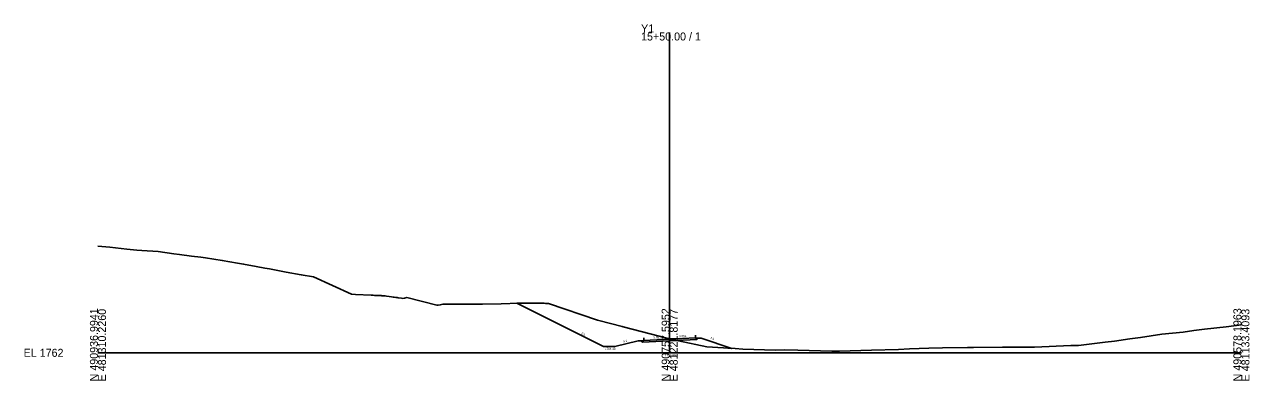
# Model space of a CAD drawing. Extents: x -26 to 403, y -10 to 6561.
# Drawn here: x -25.7 to 402.8, y 5490.3 to 5614.9 of the extents above; entities that cross this region are included whole.
import ezdxf

# ---------------------------------------------------------------- set-up
doc = ezdxf.new("R2010")
doc.units = 0
for name, color, linetype in [('Exist Cross Section Cell', 7, 'Continuous'), ('Exist XS Center Line Elevation Label', 7, 'Continuous'), ('Exist XS Ground Line', 7, 'Continuous'), ('Prop Road Sect_ Boring - Header (ID Tx)', 7, 'Continuous'), ('Prop Road Sect_ Material - Tx (Composite Desc)', 7, 'Continuous'), ('Prop XS Ditch Slope Text', 7, 'Continuous'), ('Prop XS Ditch Standard Text', 7, 'Continuous'), ('Prop XS EOT Tick Mark', 7, 'Continuous'), ('Prop XS Finish Grade', 7, 'Continuous'), ('Prop XS Finish Grade Earthwork', 7, 'Continuous'), ('Prop XS Finish Grade Pavement', 7, 'Continuous'), ('Prop XS Pvmt Edge Slope', 7, 'Continuous'), ('Prop XS SE Text', 7, 'Continuous'), ('Prop XS Side Slope Text', 7, 'Continuous'), ('Prop XS Subgrade Earthwork', 7, 'Continuous')]:
    doc.layers.add(name, color=color, linetype=linetype)

msp = doc.modelspace()

# ---------------------------------------------------------------- linework, layer by layer
at = {"layer": 'Exist Cross Section Cell'}
for p, q in [((200, 5500), (200, 5612.14)), ((0, 5500), (200, 5500)), ((200, 5500), (400, 5500))]:
    msp.add_line(p, q, dxfattribs=at)
at = {"layer": 'Exist XS Ground Line'}
msp.add_lwpolyline([(0, 5537.38), (4.21, 5536.95), (6.14, 5536.74), (10.07, 5536.31), (13.61, 5535.98), (15.36, 5535.81), (21.08, 5535.44), (26.51, 5534.7), (28.55, 5534.42), (32.7, 5533.89), (36.02, 5533.5), (37.66, 5533.23), (43.49, 5532.35), (48.81, 5531.43), (50.96, 5531.05), (55.32, 5530.26), (58.43, 5529.69), (59.96, 5529.43), (65.9, 5528.2), (71.11, 5527.33), (75.43, 5526.55), (88.69, 5520.48), (90.15, 5520.38), (95.54, 5520.17), (96.29, 5520.14), (96.76, 5520.12), (98.42, 5520.05), (99.02, 5520.03), (99.33, 5520.01), (99.87, 5519.99), (100.44, 5519.95), (100.9, 5519.88), (101.89, 5519.74), (102.75, 5519.61), (103.29, 5519.53), (103.63, 5519.48), (104.25, 5519.39), (104.64, 5519.33), (105.05, 5519.27), (106.22, 5519.09), (106.71, 5519.02), (107.23, 5519.14), (108.09, 5519.33), (118.51, 5516.73), (119.01, 5516.74), (119.75, 5516.76), (120.65, 5516.99), (121.16, 5517.01), (124.13, 5517), (127.03, 5517), (127.38, 5517), (128.1, 5517), (133.61, 5516.99), (133.95, 5516.99), (134.53, 5517.01), (141.06, 5517.18), (147.25, 5517.35), (150.02, 5517.35), (152.34, 5517.36), (153.32, 5517.36), (155.52, 5517.36), (156.09, 5517.34), (156.58, 5517.32), (157.2, 5517.3), (157.57, 5517.29), (174.74, 5511.49), (175.17, 5511.37), (183.36, 5509.23), (183.7, 5509.14), (199.5, 5505.02), (200, 5504.89), (201.63, 5504.46), (203.09, 5504.22), (212.99, 5502.14), (218.88, 5501.75), (222.9, 5501.48), (225.57, 5501.32), (237, 5500.89), (240.08, 5500.99), (244.88, 5500.89), (256.72, 5500.6), (257.48, 5500.58), (259.38, 5500.6), (270.6, 5500.88), (280.07, 5501.13), (283.86, 5501.42), (290.69, 5501.58), (295.41, 5501.73), (304.22, 5501.9), (305.23, 5501.89), (306.3, 5501.92), (316.42, 5501.98), (326.84, 5501.94), (327.58, 5501.94), (340.33, 5502.53), (343.02, 5502.62), (352.4, 5503.7), (355.62, 5504.1), (361.03, 5504.85), (364.68, 5505.31), (372.18, 5506.5), (379.62, 5507.27), (383.33, 5507.81), (387.09, 5508.27), (394.72, 5509.09), (400, 5509.83)], dxfattribs=at)
at = {"layer": 'Prop Road Sect_ Boring - Header (ID Tx)'}
for points in [[(189.91, 5504.24), (190.43, 5503.73), (191, 5504.3)], [(209.99, 5505.18), (209.52, 5504.71), (209, 5505.22)]]:
    msp.add_lwpolyline(points, close=True, dxfattribs=at)
at = {"layer": 'Prop Road Sect_ Material - Tx (Composite Desc)'}
for points in [[(155.52, 5517.36), (156.09, 5517.34), (156.58, 5517.32), (157.2, 5517.3), (157.57, 5517.29), (174.74, 5511.49), (175.17, 5511.37), (183.36, 5509.23), (183.7, 5509.14), (199.5, 5505.02), (200, 5504.89), (201.63, 5504.46), (202.37, 5504.34), (200.03, 5504.22), (190.43, 5503.73), (189.91, 5504.24), (189, 5504.2), (180.85, 5502.16), (176.85, 5502.16), (146.52, 5517.33), (147.25, 5517.35), (150.02, 5517.35), (152.34, 5517.36), (153.32, 5517.36)], [(202.37, 5504.34), (203.09, 5504.22), (212.99, 5502.14), (218.88, 5501.75), (221.75, 5501.56), (211, 5505.14), (209.99, 5505.18), (209.52, 5504.71)]]:
    msp.add_lwpolyline(points, close=True, dxfattribs=at)
at = {"layer": 'Prop XS EOT Tick Mark'}
for p, q in [((191, 5504.3), (191, 5505.3)), ((209, 5505.22), (209, 5506.22))]:
    msp.add_line(p, q, dxfattribs=at)
at = {"layer": 'Prop XS Finish Grade'}
for p, q in [((191, 5504.3), (189.91, 5504.24)), ((209, 5505.22), (209.99, 5505.18))]:
    msp.add_line(p, q, dxfattribs=at)
at = {"layer": 'Prop XS Finish Grade Earthwork'}
for p, q in [((176.85, 5502.16), (146.52, 5517.33)), ((189, 5504.2), (180.85, 5502.16)), ((189, 5504.2), (189.91, 5504.24)), ((211, 5505.14), (209.99, 5505.18)), ((211, 5505.14), (221.75, 5501.56)), ((180.85, 5502.16), (176.85, 5502.16))]:
    msp.add_line(p, q, dxfattribs=at)
at = {"layer": 'Prop XS Finish Grade Pavement'}
for p, q in [((191, 5504.3), (200, 5504.76)), ((200, 5504.76), (209, 5505.22))]:
    msp.add_line(p, q, dxfattribs=at)
at = {"layer": 'Prop XS Pvmt Edge Slope'}
for p, q in [((191, 5504.3), (190.43, 5503.73)), ((209, 5505.22), (209.52, 5504.71))]:
    msp.add_line(p, q, dxfattribs=at)
at = {"layer": 'Prop XS Subgrade Earthwork'}
for p, q in [((189.91, 5504.24), (190.43, 5503.73)), ((190.43, 5503.73), (200.03, 5504.22)), ((200.03, 5504.22), (209.52, 5504.71)), ((209.99, 5505.18), (209.52, 5504.71))]:
    msp.add_line(p, q, dxfattribs=at)

# ---------------------------------------------------------------- texts
at = {"layer": 'Exist Cross Section Cell'}
for s, p in [('Y1', (190, 5612.14)), ('15+50.00 / 1', (190, 5609.34)), ('EL 1762', (-26, 5498.6))]:
    msp.add_text(s, height=2.8, dxfattribs=at).set_placement(p)
for s, p in [('N 490936.9941', (0, 5490)), ('E 481310.2260', (2.8, 5490)), ('N 490757.5952', (200, 5490)), ('N 490578.1963', (400, 5490)), ('E 481133.4093', (402.8, 5490)), ('E 481221.8177', (202.8, 5490))]:
    msp.add_text(s, height=2.8, rotation=90, dxfattribs=at).set_placement(p)
at = {"layer": 'Exist XS Center Line Elevation Label'}
msp.add_text('1766.89', height=0.75, dxfattribs=at).set_placement((198.39, 5498.72))
at = {"layer": 'Prop XS Ditch Slope Text'}
msp.add_text('4:1', height=0.75, rotation=14.0362, dxfattribs=at).set_placement((183.8, 5503.53))
at = {"layer": 'Prop XS Ditch Standard Text'}
msp.add_text('1764.16', height=0.75, dxfattribs=at).set_placement((177.31, 5501.01))
at = {"layer": 'Prop XS SE Text'}
for p in [(194.32, 5504.97), (203.32, 5505.43)]:
    msp.add_text('0.051', height=0.75, rotation=2.9386, dxfattribs=at).set_placement(p)
at = {"layer": 'Prop XS Side Slope Text'}
for s, rotation, p in [('2:1', 333.4349, (169.03, 5506.58)), ('3:1', 341.5651, (214.15, 5504.91))]:
    msp.add_text(s, height=0.75, rotation=rotation, dxfattribs=at).set_placement(p)

doc.saveas('drawing.dxf')
